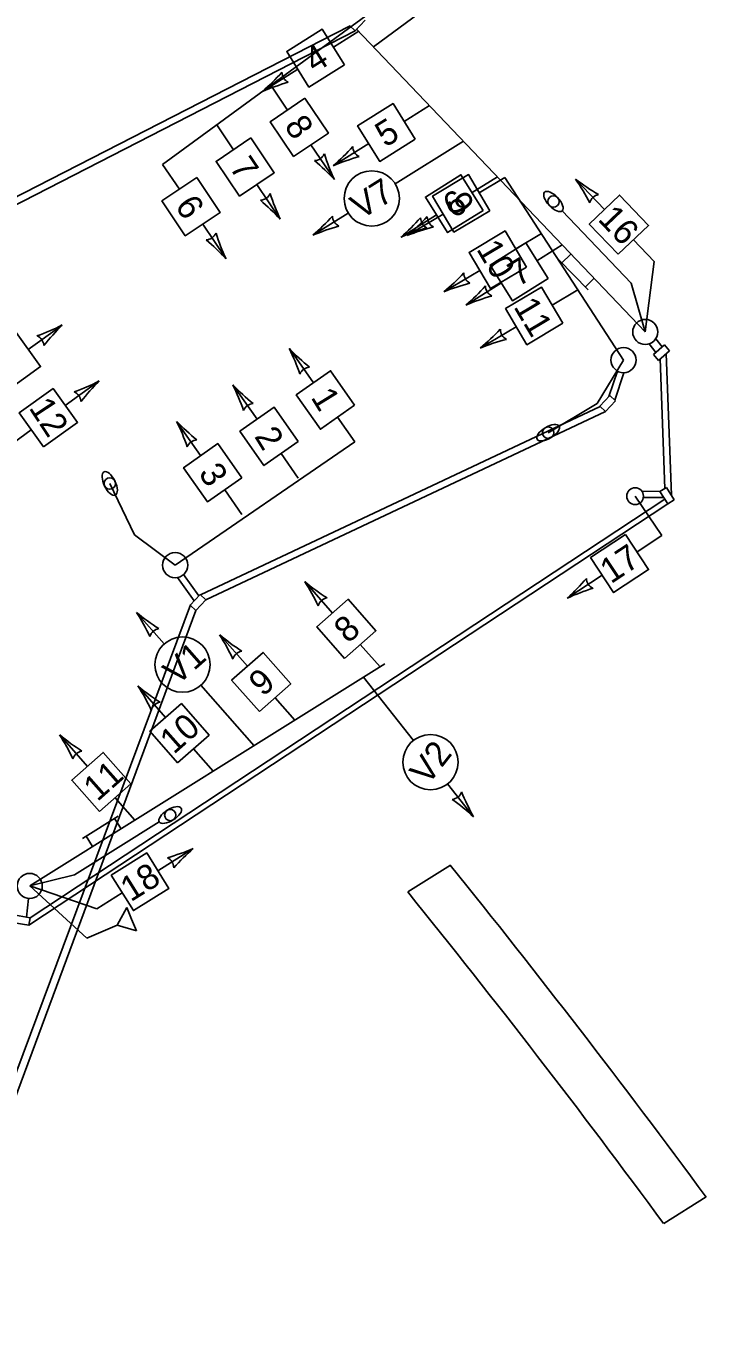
# Model space of a CAD drawing. Extents: x 982100 to 1292532, y 220574 to 1843876.
# Drawn here: x 984552 to 984633.2, y 1843256.9 to 1843411.6 of the extents above; entities that cross this region are included whole.
import ezdxf

# ---------------------------------------------------------------- set-up
doc = ezdxf.new("R2010")
doc.units = 0
for name, color, linetype in [('5', 7, 'Continuous'), ('R_Existing Luminaire', 7, 'Continuous'), ('R_Existing Signal', 7, 'Continuous'), ('R_Existing Signal Heads', 7, 'Continuous'), ('R_Existing Signal Mast Arm', 7, 'Continuous'), ('V-SIGNAL-CONDUIT', 7, 'Continuous'), ('V-SIGNAL-HEAD', 7, 'Continuous'), ('V-SIGNAL-MAST', 7, 'Continuous')]:
    doc.layers.add(name, color=color, linetype=linetype)

msp = doc.modelspace()

# ---------------------------------------------------------------- linework, layer by layer
at = {"layer": '5'}
for p, q in [((984625.9, 1843375.13), (984591.4, 1843411.32)), ((984552.41, 1843309.02), (984594.81, 1843335.51))]:
    msp.add_line(p, q, dxfattribs=at)
at = {"layer": 'R_Existing Luminaire'}
for p, q in [((984623.31, 1843371.77), (984620.15, 1843366.6)), ((984620.15, 1843366.6), (984614.31, 1843363.11)), ((984564.92, 1843350.92), (984561.98, 1843357.04)), ((984569.78, 1843347.3), (984564.92, 1843350.92))]:
    msp.add_line(p, q, dxfattribs=at)
for centre in [(984614.31, 1843363.11), (984561.97, 1843357.04)]:
    msp.add_circle(centre, 0.679, dxfattribs=at)
for centre, major_axis in [((984614.31, 1843363.11), (-1.32, -0.79)), ((984561.97, 1843357.04), (-0.67, 1.39))]:
    msp.add_ellipse(centre, major_axis=major_axis, ratio=0.441176, dxfattribs=at)
at = {"layer": 'R_Existing Signal'}
for p, q in [((984590.58, 1843411.68), (984591.25, 1843411.05)), ((984591.25, 1843411.05), (984592.45, 1843412.32)), ((984541.29, 1843386.39), (984590.61, 1843411.62)), ((984541.9, 1843385.8), (984591.25, 1843411.05)), ((984621.56, 1843367.43), (984622.57, 1843370.46)), ((984622.26, 1843367), (984623.35, 1843370.27)), ((984621.67, 1843367.55), (984620.47, 1843366.28)), ((984621.14, 1843365.65), (984622.34, 1843366.92)), ((984622.34, 1843366.92), (984621.67, 1843367.55)), ((984572.81, 1843343.74), (984620.51, 1843366.24)), ((984573.44, 1843343.15), (984621.14, 1843365.65)), ((984620.47, 1843366.28), (984621.14, 1843365.65)), ((984572.06, 1843343.04), (984570.06, 1843345.83)), ((984572.62, 1843343.63), (984570.78, 1843346.18)), ((984572.77, 1843343.78), (984571.57, 1843342.51)), ((984573.44, 1843343.15), (984572.77, 1843343.78)), ((984539.64, 1843256.94), (984571.61, 1843342.55)), ((984571.57, 1843342.51), (984572.23, 1843341.88)), ((984572.23, 1843341.88), (984573.44, 1843343.15)), ((984540.69, 1843256.86), (984572.24, 1843341.88))]:
    msp.add_line(p, q, dxfattribs=at)
for centre in [(984623.31, 1843371.77), (984569.78, 1843347.3)]:
    msp.add_circle(centre, 1.5, dxfattribs=at)
at = {"layer": 'R_Existing Signal Heads'}
for p, q in [((984581.21, 1843404.57), (984583.2, 1843401.61)), ((984574.74, 1843399.84), (984576.74, 1843396.88)), ((984585.99, 1843397.46), (984588.78, 1843393.32)), ((984568.28, 1843395.12), (984570.28, 1843392.15)), ((984609.15, 1843393.57), (984606.08, 1843391.75)), ((984579.53, 1843392.73), (984582.32, 1843388.59)), ((984601.78, 1843389.19), (984597.49, 1843386.64)), ((984573.07, 1843388.01), (984575.86, 1843383.86)), ((984613.51, 1843386.86), (984610.44, 1843385.04)), ((984606.14, 1843382.48), (984601.85, 1843379.93)), ((984617.87, 1843380.14), (984614.8, 1843378.32)), ((984552.24, 1843373.03), (984556.29, 1843375.95)), ((984610.5, 1843375.76), (984606.21, 1843373.21)), ((984586.28, 1843369.05), (984583.41, 1843373.14)), ((984556.66, 1843366.36), (984560.72, 1843369.28)), ((984579.55, 1843364.71), (984576.68, 1843368.8)), ((984572.82, 1843360.37), (984569.95, 1843364.46)), ((984591.21, 1843362.03), (984589.15, 1843364.96)), ((984549.71, 1843361.35), (984552.6, 1843363.43)), ((984584.48, 1843357.69), (984582.42, 1843360.62)), ((984577.75, 1843353.35), (984575.7, 1843356.28))]:
    msp.add_line(p, q, dxfattribs=at)
for points in [[(984585.27, 1843403.01), (984581.12, 1843400.21), (984583.92, 1843396.07), (984588.07, 1843398.86)], [(984578.81, 1843398.28), (984574.66, 1843395.49), (984577.46, 1843391.34), (984581.61, 1843394.13)], [(984572.35, 1843393.55), (984568.2, 1843390.76), (984570.99, 1843386.61), (984575.15, 1843389.4)], [(984607.36, 1843389.6), (984604.8, 1843393.9), (984600.51, 1843391.35), (984603.06, 1843387.04)], [(984611.72, 1843382.88), (984609.16, 1843387.19), (984604.87, 1843384.63), (984607.42, 1843380.33)], [(984616.08, 1843376.17), (984613.52, 1843380.47), (984609.22, 1843377.91), (984611.78, 1843373.61)], [(984549.65, 1843368.08), (984546.72, 1843372.14), (984550.78, 1843375.06), (984553.7, 1843371)], [(984591.2, 1843366.39), (984587.11, 1843363.52), (984584.23, 1843367.61), (984588.33, 1843370.49)], [(984554.07, 1843361.41), (984551.14, 1843365.46), (984555.2, 1843368.38), (984558.13, 1843364.33)], [(984584.47, 1843362.05), (984580.38, 1843359.18), (984577.51, 1843363.27), (984581.6, 1843366.15)], [(984577.74, 1843357.71), (984573.65, 1843354.84), (984570.78, 1843358.93), (984574.87, 1843361.81)]]:
    msp.add_lwpolyline(points, close=True, dxfattribs=at)
for centre, radius, start, end in [((984586.36, 1843396.92), 1.34, 272.0983, 335.793), ((984610.74, 1843403.71), 24.29, 197.5992, 205.3373), ((984570.89, 1843376.89), 24.29, 42.554, 50.2921), ((984579.9, 1843392.19), 1.34, 272.0983, 335.793), ((984604.27, 1843398.98), 24.29, 197.5992, 205.3373), ((984564.43, 1843372.16), 24.29, 42.554, 50.2921), ((984582.09, 1843405.43), 24.29, 309.3397, 317.0778), ((984601.22, 1843388.86), 1.34, 178.8841, 242.5787), ((984573.43, 1843387.46), 1.34, 272.0983, 335.793), ((984597.81, 1843394.25), 24.29, 197.5992, 205.3373), ((984606.64, 1843364.14), 24.29, 104.3849, 112.1231), ((984557.96, 1843367.43), 24.29, 42.554, 50.2921), ((984586.45, 1843398.71), 24.29, 309.3397, 317.0778), ((984611, 1843357.42), 24.29, 104.3849, 112.1231), ((984605.58, 1843382.15), 1.34, 178.8841, 242.5787), ((984545.2, 1843397.57), 24.29, 289.426, 297.1642), ((984552.77, 1843373.42), 1.34, 3.9252, 67.6198), ((984573.28, 1843358.59), 24.29, 134.3808, 142.1189), ((984590.81, 1843392), 24.29, 309.3397, 317.0778), ((984609.94, 1843375.43), 1.34, 178.8841, 242.5787), ((984600.97, 1843389.92), 24.29, 223.691, 231.4292), ((984561.66, 1843362.31), 24.29, 18.7363, 26.4744), ((984615.35, 1843350.71), 24.29, 104.3849, 112.1231), ((984585.9, 1843369.58), 1.34, 93.2354, 156.93), ((984549.63, 1843390.89), 24.29, 289.426, 297.1642), ((984577.71, 1843351.92), 24.29, 134.3808, 142.1189), ((984594.24, 1843385.58), 24.29, 223.691, 231.4292), ((984554.93, 1843357.97), 24.29, 18.7363, 26.4744), ((984557.19, 1843366.74), 1.34, 3.9252, 67.6198), ((984579.17, 1843365.24), 1.34, 93.2354, 156.93), ((984587.52, 1843381.24), 24.29, 223.691, 231.4292), ((984548.21, 1843353.63), 24.29, 18.7363, 26.4744), ((984572.45, 1843360.9), 1.34, 93.2354, 156.93)]:
    msp.add_arc(centre, radius, start, end, dxfattribs=at)
at = {"layer": 'R_Existing Signal Mast Arm'}
for p, q in [((984595.72, 1843415.2), (984568.28, 1843395.12)), ((984595.72, 1843415.2), (984568.28, 1843395.12)), ((984623.31, 1843371.77), (984609.15, 1843393.57)), ((984623.31, 1843371.77), (984609.15, 1843393.57)), ((984569.78, 1843347.3), (984591.21, 1843362.03)), ((984569.78, 1843347.3), (984591.21, 1843362.03))]:
    msp.add_line(p, q, dxfattribs=at)
at = {"layer": 'V-SIGNAL-CONDUIT'}
for p, q in [((984627.17, 1843372.69), (984626.38, 1843373.71)), ((984628.19, 1843373.58), (984626.87, 1843372.43)), ((984627.93, 1843373.35), (984627.16, 1843374.32)), ((984628.79, 1843372.89), (984628.19, 1843373.58)), ((984626.87, 1843372.43), (984627.48, 1843371.74)), ((984627.48, 1843371.74), (984628.79, 1843372.89)), ((984627.67, 1843371.91), (984628.24, 1843356.46)), ((984628.4, 1843372.55), (984629.02, 1843355.65)), ((984627.65, 1843356.1), (984625.5, 1843356.12)), ((984627.66, 1843356.1), (984628.43, 1843356.58)), ((984628.58, 1843354.61), (984627.66, 1843356.1)), ((984628.43, 1843356.58), (984629.36, 1843355.1)), ((984628.58, 1843354.61), (984552.29, 1843304.32)), ((984628.23, 1843355.18), (984552.45, 1843305.23)), ((984628.12, 1843355.36), (984625.67, 1843355.37)), ((984629.36, 1843355.1), (984628.58, 1843354.61)), ((984597.54, 1843308.3), (984602.63, 1843311.48)), ((984552.04, 1843305.3), (984552.25, 1843307.53)), ((984550.72, 1843305.53), (984552.45, 1843305.23)), ((984552.45, 1843305.23), (984552.29, 1843304.32)), ((984552.29, 1843304.32), (984550.57, 1843304.63)), ((984628.1, 1843268.73), (984633.16, 1843271.9))]:
    msp.add_line(p, q, dxfattribs=at)
for centre, radius, start, end in [((983721.72, 1842600.34), 1132.13, 36.38306, 38.91336), ((983721.76, 1842600.36), 1126.13, 36.40649, 38.95041)]:
    msp.add_arc(centre, radius, start, end, dxfattribs=at)
at = {"layer": 'V-SIGNAL-HEAD'}
for p, q in [((984593.47, 1843409.15), (984601.17, 1843414.9)), ((984591.7, 1843411.02), (984588.67, 1843409.13)), ((984584.43, 1843406.47), (984580.19, 1843403.83)), ((984600.15, 1843402.15), (984597.12, 1843400.26)), ((984604.2, 1843397.9), (984596.05, 1843392.81)), ((984592.88, 1843397.61), (984588.64, 1843394.96)), ((984608.25, 1843393.65), (984605.22, 1843391.76)), ((984621.03, 1843389.74), (984617.58, 1843393.36)), ((984590.45, 1843389.31), (984586.22, 1843386.67)), ((984600.98, 1843389.11), (984596.74, 1843386.46)), ((984624.23, 1843380.95), (984616, 1843389.58)), ((984615.99, 1843385.52), (984612.96, 1843383.63)), ((984626.95, 1843383.54), (984624.48, 1843386.12)), ((984608.73, 1843380.98), (984604.49, 1843378.33)), ((984624.69, 1843355.53), (984627.9, 1843350.85)), ((984627.9, 1843350.85), (984624.92, 1843348.89)), ((984588.57, 1843341.58), (984585.26, 1843345.33)), ((984620.76, 1843346.12), (984616.59, 1843343.37)), ((984568.47, 1843337.91), (984565.17, 1843341.66)), ((984578.4, 1843335.23), (984575.09, 1843338.97)), ((984594.24, 1843335.15), (984591.88, 1843337.83)), ((984568.64, 1843329.13), (984565.33, 1843332.88)), ((984579.19, 1843325.75), (984572.83, 1843332.96)), ((984592.27, 1843333.92), (984598.22, 1843326.38)), ((984584.07, 1843328.8), (984581.7, 1843331.48)), ((984559.3, 1843323.29), (984555.99, 1843327.04)), ((984574.31, 1843322.7), (984571.95, 1843325.38)), ((984602.3, 1843321.2), (984605.4, 1843317.28)), ((984564.97, 1843316.87), (984562.61, 1843319.54)), ((984557.77, 1843310.35), (984567.88, 1843316.66)), ((984567.7, 1843310.84), (984571.94, 1843313.49)), ((984560.44, 1843306.29), (984563.46, 1843308.19)), ((984564.57, 1843305.05), (984563.99, 1843306.43)), ((984565.15, 1843303.67), (984564.57, 1843305.05)), ((984559.23, 1843302.8), (984562.86, 1843304.33))]:
    msp.add_line(p, q, dxfattribs=at)
for points in [[(984589.99, 1843407), (984587.34, 1843411.25), (984583.1, 1843408.6), (984585.75, 1843404.35)], [(984598.44, 1843398.13), (984595.79, 1843402.38), (984591.55, 1843399.73), (984594.2, 1843395.48)], [(984606.54, 1843389.63), (984603.89, 1843393.88), (984599.65, 1843391.23), (984602.3, 1843386.98)], [(984622.67, 1843384.4), (984626.29, 1843387.85), (984622.84, 1843391.46), (984619.22, 1843388.01)], [(984614.29, 1843381.5), (984611.64, 1843385.75), (984607.4, 1843383.1), (984610.05, 1843378.85)], [(984623.54, 1843350.96), (984626.3, 1843346.78), (984622.12, 1843344.03), (984619.37, 1843348.21)], [(984590, 1843336.18), (984593.75, 1843339.48), (984590.44, 1843343.23), (984586.69, 1843339.93)], [(984579.83, 1843329.82), (984583.58, 1843333.13), (984580.27, 1843336.88), (984576.52, 1843333.57)], [(984570.07, 1843323.73), (984573.82, 1843327.03), (984570.52, 1843330.78), (984566.76, 1843327.48)], [(984560.73, 1843317.89), (984564.48, 1843321.2), (984561.17, 1843324.95), (984557.42, 1843321.64)], [(984562.14, 1843310.31), (984564.79, 1843306.07), (984569.03, 1843308.72), (984566.38, 1843312.96)]]:
    msp.add_lwpolyline(points, close=True, dxfattribs=at)
msp.add_lwpolyline([(984565.15, 1843303.67), (984562.86, 1843304.33), (984563.99, 1843306.43)], dxfattribs=at)
for centre, radius in [((984593.25, 1843391.06), 3.3), ((984614.94, 1843390.69), 0.679), ((984570.65, 1843335.43), 3.3), ((984600.26, 1843323.79), 3.3), ((984569.19, 1843317.48), 0.679)]:
    msp.add_circle(centre, radius, dxfattribs=at)
for centre, radius, start, end in [((984564.38, 1843422.27), 24.29, 310.6082, 318.3463), ((984583.87, 1843406.13), 1.34, 180.1525, 243.8472), ((984589.83, 1843381.53), 24.29, 105.6534, 113.3915), ((984572.83, 1843413.4), 24.29, 310.6082, 318.3463), ((984592.32, 1843397.26), 1.34, 180.1525, 243.8472), ((984598.28, 1843372.66), 24.29, 105.6534, 113.3915), ((984597.69, 1843379.4), 24.29, 27.3115, 35.0496), ((984632.45, 1843412.57), 24.29, 232.2662, 240.0043), ((984620.58, 1843390.21), 1.34, 101.8106, 165.5052), ((984570.4, 1843405.11), 24.29, 310.6082, 318.3463), ((984589.9, 1843388.97), 1.34, 180.1525, 243.8472), ((984580.93, 1843404.9), 24.29, 310.6082, 318.3463), ((984600.42, 1843388.76), 1.34, 180.1525, 243.8472), ((984595.86, 1843364.37), 24.29, 105.6534, 113.3915), ((984606.38, 1843364.16), 24.29, 105.6534, 113.3915), ((984588.68, 1843396.77), 24.29, 310.6082, 318.3463), ((984614.13, 1843356.03), 24.29, 105.6534, 113.3915), ((984608.17, 1843380.63), 1.34, 180.1525, 243.8472), ((984564.84, 1843332.17), 24.29, 25.0666, 32.8047), ((984600.87, 1843363.94), 24.29, 230.0213, 237.7595), ((984600.34, 1843361.42), 24.29, 312.017, 319.7551), ((984620.22, 1843345.76), 1.34, 181.5613, 245.256), ((984626.79, 1843321.32), 24.29, 107.0622, 114.8003), ((984588.13, 1843342.07), 1.34, 99.5657, 163.2603), ((984544.75, 1843328.5), 24.29, 25.0505, 32.7887), ((984580.78, 1843360.27), 24.29, 230.0053, 237.7434), ((984568.04, 1843338.4), 1.34, 99.5497, 163.2443), ((984554.67, 1843325.81), 24.29, 25.0666, 32.8047), ((984590.7, 1843357.59), 24.29, 230.0213, 237.7595), ((984577.96, 1843335.72), 1.34, 99.5657, 163.2603), ((984544.92, 1843319.72), 24.29, 25.0666, 32.8047), ((984580.94, 1843351.49), 24.29, 230.0213, 237.7595), ((984568.21, 1843329.62), 1.34, 99.5657, 163.2603), ((984535.57, 1843313.88), 24.29, 25.0666, 32.8047), ((984571.6, 1843345.66), 24.29, 230.0213, 237.7595), ((984558.86, 1843323.79), 1.34, 99.5657, 163.2603), ((984602.71, 1843320.68), 1.34, 276.4199, 340.1145), ((984588.79, 1843299.55), 24.29, 46.8755, 54.6136), ((984626.51, 1843329.3), 24.29, 201.9208, 209.6589), ((984562.29, 1843335.78), 24.29, 285.6695, 293.4076), ((984587.76, 1843295.05), 24.29, 130.6242, 138.3623), ((984568.26, 1843311.19), 1.34, 0.1686, 63.8632)]:
    msp.add_arc(centre, radius, start, end, dxfattribs=at)
for centre, major_axis in [((984614.94, 1843390.69), (1.06, -1.11)), ((984569.19, 1843317.48), (-1.31, -0.82))]:
    msp.add_ellipse(centre, major_axis=major_axis, ratio=0.441176, dxfattribs=at)
at = {"layer": 'V-SIGNAL-MAST'}
for p, q in [((984615.95, 1843383.37), (984616.98, 1843384.39)), ((984615.6, 1843383.73), (984619.1, 1843380.16)), ((984625.9, 1843375.13), (984626.95, 1843383.54)), ((984618.75, 1843380.52), (984619.79, 1843381.54)), ((984625.9, 1843375.13), (984624.23, 1843380.95)), ((984562.97, 1843317.33), (984558.73, 1843314.68)), ((984562.54, 1843317.06), (984563.31, 1843315.83)), ((984559.15, 1843314.94), (984559.92, 1843313.71)), ((984552.41, 1843309.02), (984557.77, 1843310.35)), ((984552.41, 1843309.02), (984560.44, 1843306.29)), ((984559.23, 1843302.8), (984552.41, 1843309.02))]:
    msp.add_line(p, q, dxfattribs=at)
for centre, radius in [((984625.9, 1843375.13), 1.5), ((984624.69, 1843355.53), 1), ((984552.41, 1843309.02), 1.5)]:
    msp.add_circle(centre, radius, dxfattribs=at)

# ---------------------------------------------------------------- texts
at = {"layer": 'R_Existing Signal Heads'}
for s, rotation, p in [('8', 303.9479, (984582.73, 1843399.71)), ('7', 303.9479, (984576.18, 1843394.77)), ('9', 300.7336, (984601.94, 1843390.69)), ('6', 303.9479, (984569.68, 1843390.16)), ('10', 300.7336, (984605.68, 1843385.02)), ('11', 300.7336, (984610.12, 1843378.14)), ('1', 301.6628, (984585.91, 1843367.33)), ('12', 303.2795, (984552.24, 1843366.08)), ('2', 301.6628, (984579.17, 1843362.67)), ('3', 301.6628, (984572.5, 1843358.31))]:
    msp.add_text(s, height=3, rotation=rotation, dxfattribs=at).set_placement(p)
at = {"layer": 'V-SIGNAL-HEAD'}
for s, rotation, p in [('4', 32.0021, (984586.44, 1843405.96)), ('5', 32.0021, (984594.88, 1843397.09)), ('V7', 31.9988, (984591.95, 1843388.48)), ('6', 32.0021, (984602.99, 1843388.59)), ('16', 313.6992, (984620.14, 1843388.5)), ('7', 32.0021, (984610.73, 1843380.46)), ('17', 33.5076, (984621.8, 1843345.01)), ('8', 41.5001, (984590.41, 1843337.87)), ('V1', 41.396, (984570.01, 1843332.87)), ('9', 41.5001, (984580.24, 1843331.52)), ('10', 41.5001, (984569.62, 1843324.65)), ('V2', 51.9442, (984599.93, 1843320.93)), ('11', 41.5001, (984560.49, 1843319.01)), ('18', 32.0182, (984564.47, 1843307.05))]:
    msp.add_text(s, height=3, rotation=rotation, dxfattribs=at).set_placement(p)

doc.saveas('drawing.dxf')
